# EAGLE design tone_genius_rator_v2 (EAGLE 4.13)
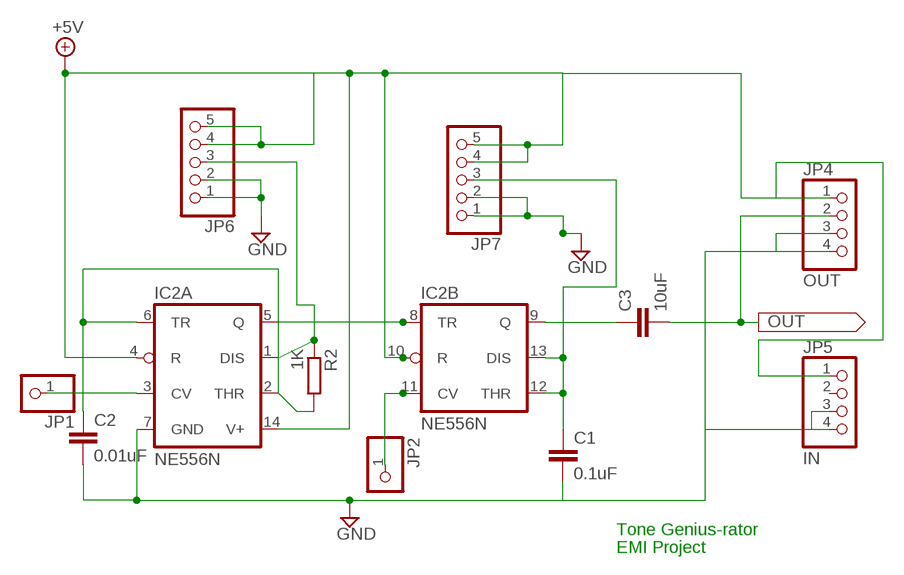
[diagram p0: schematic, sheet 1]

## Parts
C1  0.1uF  C-EU025-024X044  [C025-024X044]
C2  0.01uF  C-EU025-024X044  [C025-024X044]
C3  10uF  C-EU025-024X044  [C025-024X044]
IC2  NE556N  [DIL14]
JP1  PINHD-1X1  [1X01]
JP2  PINHD-1X1  [1X01]
JP4  OUT  PINHD-1X4  [1X04]
JP5  IN  PINHD-1X4  [1X04]
JP6  PINHD-1X5  [1X05]
JP7  PINHD-1X5  [1X05]
R2  1K  R-EU_0204/7  [0204/7]

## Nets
+5V: IC2.4(A:R) IC2.10(B:R) IC2.14(A:V+) JP4.1 JP5.1 JP6.4 JP6.5 JP7.4 JP7.5
GND: C1.2 C2.2 IC2.7(A:GND) JP4.3 JP4.4 JP5.3 JP5.4 JP6.1 JP6.2 JP7.1 JP7.2
N$1: IC2.5(A:Q) IC2.8(B:TR)
N$2: C1.1 IC2.12(B:THR) IC2.13(B:DIS) JP7.3
N$3: IC2.3(A:CV) JP1.1
N$4: C3.1 IC2.9(B:Q)
N$5: C2.1 IC2.2(A:THR) IC2.6(A:TR) R2.2
N$6: C3.2 JP4.2
N$8: IC2.11(B:CV) JP2.1
N$10: IC2.1(A:DIS) JP6.3 R2.1
Unconnected: JP5.2

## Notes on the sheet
- Tone Genius-rator
- EMI Project

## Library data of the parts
C1-C3 = rcl:C-EU: CAPACITOR, European symbol
IC2 = linear:*556: Dual TIMER
JP1 JP2 = pinhead:PINHD-1X1: PIN HEADER
JP4 JP5 = pinhead:PINHD-1X4: PIN HEADER
JP6 JP7 = pinhead:PINHD-1X5: PIN HEADER
R2 = rcl:R-EU_: RESISTOR, European symbol

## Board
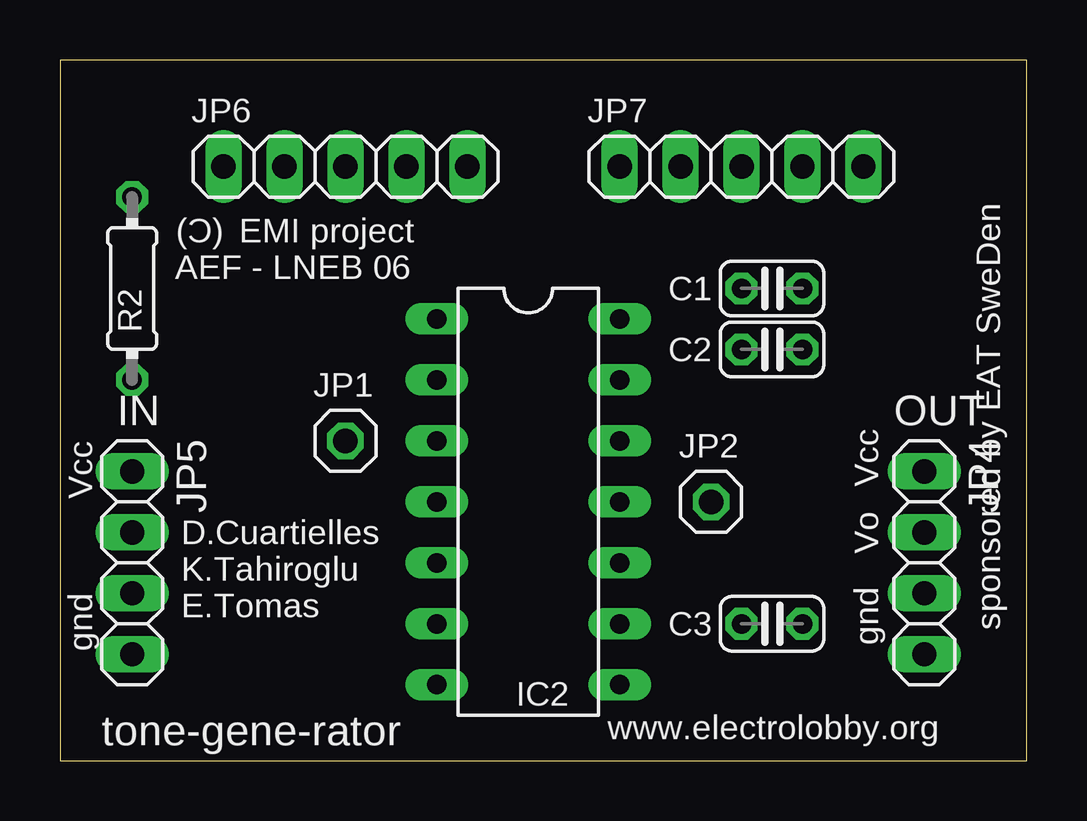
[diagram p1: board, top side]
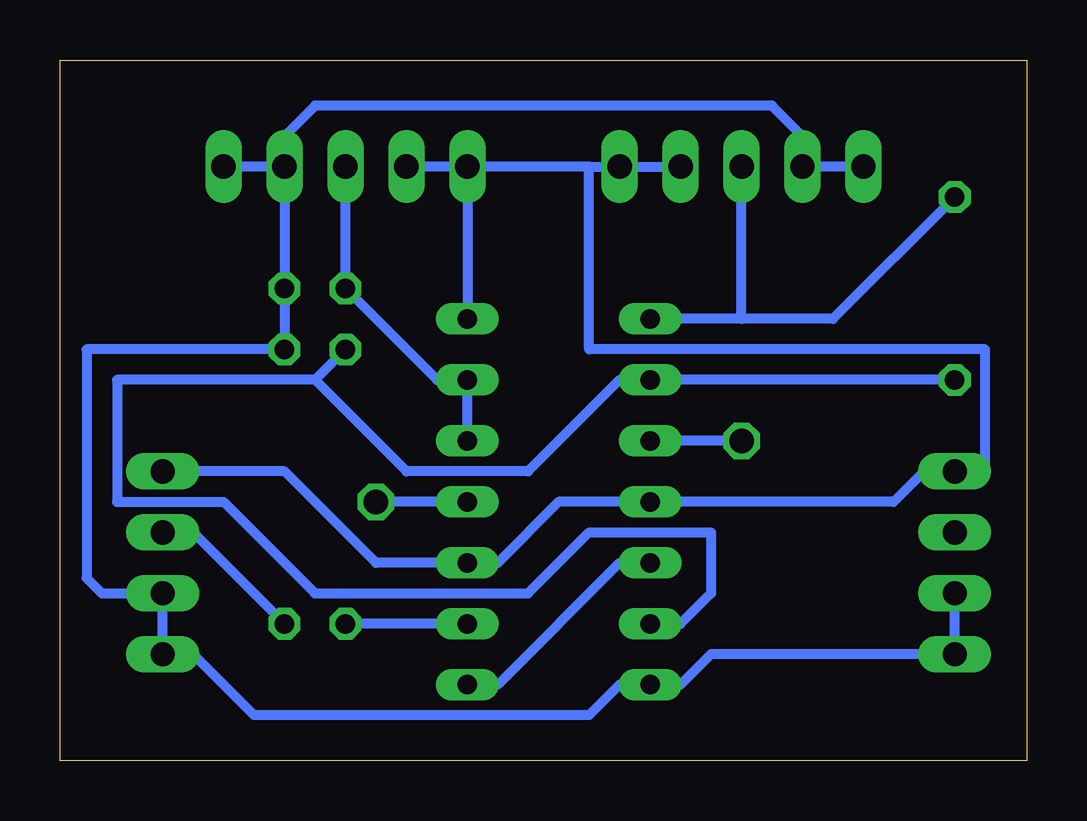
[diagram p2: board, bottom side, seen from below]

Size 40.31 x 29.2 mm. Coordinates in mm from the lower left corner, seen from the top.
Outline: 0,0 40.31,0 40.31,29.2 0,29.2 0,0
Copper layers (1*16): Top 0.035mm / dielectric 1.5mm / Bottom 0.035mm
Design rules "default": minimum track width 10mil, minimum drill 24mil, track to track 8mil, track to pad 8mil, pad to pad 8mil, via to via 8mil, smd to smd 8mil, copper to edge 40mil, drill to drill 8mil, minimum pad ring 10mil, minimum via ring 8mil, stop-mask expansion 4mil, vias tented up to drill 0mil, thermal gap 10mil

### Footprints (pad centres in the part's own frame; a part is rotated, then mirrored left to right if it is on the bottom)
C025-024X044 = drill 0.813 octagon: 1 -1.27,0; 2 1.27,0
DIL14 = drill 0.813 long: 1 -7.62,-3.81; 2 -5.08,-3.81; 3 -2.54,-3.81; 4 0,-3.81; 5 2.54,-3.81; 6 5.08,-3.81; 7 7.62,-3.81; 8 7.62,3.81; 9 5.08,3.81; 10 2.54,3.81; 11 0,3.81; 12 -2.54,3.81; 13 -5.08,3.81; 14 -7.62,3.81
1X01 = drill 1.016 octagon: 1 0,0
1X04 = drill 1.016 long: 1 -3.81,0; 2 -1.27,0; 3 1.27,0; 4 3.81,0
1X05 = drill 1.016 long: 1 -5.08,0; 2 -2.54,0; 3 0,0; 4 2.54,0; 5 5.08,0
0204/7 = drill 0.813 octagon: 1 -3.81,0; 2 3.81,0

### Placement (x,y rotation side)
C1  29.68,19.68 0 top
C2  29.68,17.14 0 top
C3  29.68,5.71 0 top
IC2  19.52,10.79 270 top
JP1  11.9,13.33 0 top
JP2  27.14,10.79 0 top
JP4  36.03,8.25 270 top
JP5  3.01,8.25 270 top
JP6  11.9,24.76 0 top
JP7  28.41,24.76 180 top
R2  3.01,19.68 270 top

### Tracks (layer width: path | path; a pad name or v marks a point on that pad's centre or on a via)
+5V
  Bottom 0.406: JP6.4 JP6.5 18.25,24.76 | JP7.5 IC2.14 | JP7.5 JP7.4 | 18.25,24.76 JP7.5 | JP4.1 30.95,12.06 27.14,8.25 IC2.10 22.06,8.25 19.52,10.79 IC2.4 5.55,10.79 4.28,12.06 JP5.1 1.74,12.06 1.74,17.14 18.25,17.14 18.25,24.76
GND
  Bottom 0.406: JP5.3 JP5.4 13.17,4.44 14.44,3.17 IC2.7 16.98,3.17 18.25,1.9 32.22,1.9 34.76,4.44 JP4.4 JP4.3 38.57,6.98 39.2,7.62 39.2,17.14 C2.2 C1.2 JP7.2 | JP6.1 JP6.2 9.36,26.03 10.63,27.3 29.68,27.3 30.95,26.03 JP7.2 | JP7.2 JP7.1
N$1
  Bottom 0.406: IC2.5 16.98,8.25 22.06,3.17 IC2.8
N$2
  Bottom 0.406: IC2.12 IC2.13 24.6,15.87 C1.1 JP7.3
N$3
  Bottom 0.406: JP1.1 IC2.3
N$4
  Bottom 0.406: IC2.9 C3.1
N$5
  Bottom 0.406: R2.2 IC2.2 16.98,15.87 20.79,12.06 25.87,12.06 29.68,15.87 | 29.68,15.87 37.94,15.87 37.94,10.79 33.49,10.79 29.68,6.98 20.79,6.98 18.25,9.52 13.17,9.52 13.17,6.98 14.44,5.71 IC2.6 | 29.68,15.87 C2.1
N$6
  Bottom 0.406: C3.2 34.76,9.52 JP4.2
N$8
  Bottom 0.406: IC2.11 JP2.1
N$10
  Bottom 0.406: R2.1 8.09,18.41 11.9,18.41 | 11.9,18.41 IC2.1 | 11.9,18.41 JP6.3

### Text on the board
tPlace: (C) | EMI project | AEF - LNEB 06 | Vcc | Vcc | D.Cuartielles | Vo | K.Tahiroglu | E.Tomas | sponsored by EAT SweDen | gnd | gnd | tone-gene-rator | www.electrolobby.org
